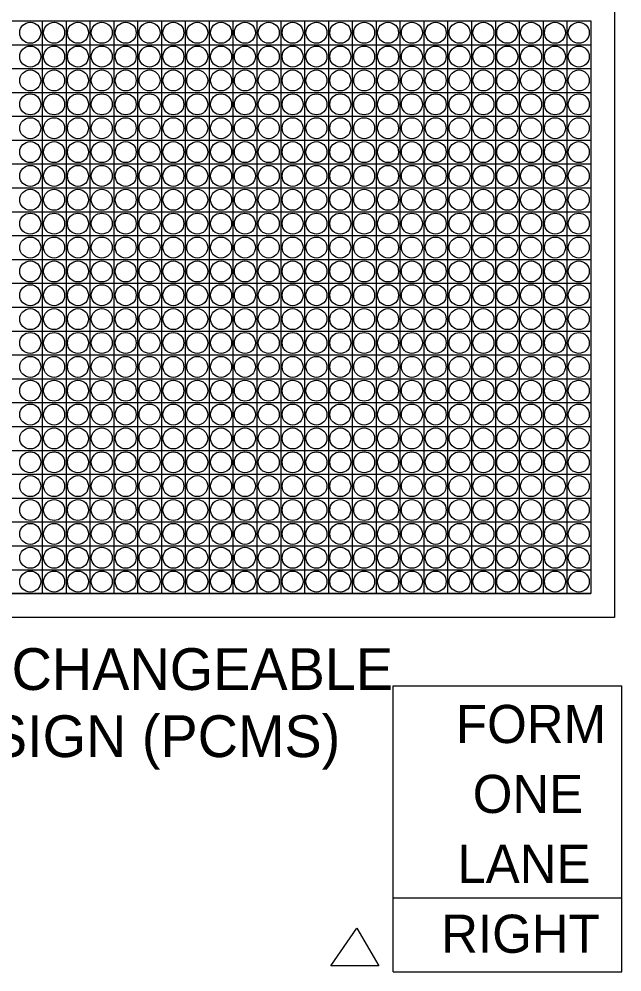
# Model space of a CAD drawing. Extents: x 15278 to 18126, y 1908 to 6555.
# Drawn here: x 16378.4 to 16479.5, y 2488.5 to 2648.2 of the extents above; entities that cross this region are included whole.
import ezdxf

# ---------------------------------------------------------------- set-up
doc = ezdxf.new("R2010")
doc.units = 0
for name, color, linetype in [('TRAFFIC_SIGNS_PR', 7, 'Continuous'), ('TYPICAL_TEXT_DIMEN_EX', 7, 'Continuous'), ('TYPICAL_TEXT_DIMEN_PR', 7, 'Continuous')]:
    doc.layers.add(name, color=color, linetype=linetype)

msp = doc.modelspace()

# ---------------------------------------------------------------- linework, layer by layer
at = {"layer": 'TRAFFIC_SIGNS_PR'}
for p, q in [((16382.29, 2647.89), (16382.29, 2551.89)), ((16386.29, 2647.89), (16386.29, 2551.89)), ((16390.29, 2647.89), (16390.29, 2551.89)), ((16394.29, 2647.89), (16394.29, 2551.89)), ((16398.29, 2647.89), (16398.29, 2551.89)), ((16402.29, 2647.89), (16402.29, 2551.89)), ((16406.29, 2647.89), (16406.29, 2551.89)), ((16410.29, 2647.89), (16410.29, 2551.89)), ((16414.29, 2647.89), (16414.29, 2551.89)), ((16418.29, 2647.89), (16418.29, 2551.89)), ((16422.29, 2647.89), (16422.29, 2551.89)), ((16426.29, 2647.89), (16426.29, 2551.89)), ((16430.29, 2647.89), (16430.29, 2551.89)), ((16434.29, 2647.89), (16434.29, 2551.89)), ((16438.29, 2647.89), (16438.29, 2551.89)), ((16442.29, 2647.89), (16442.29, 2551.89)), ((16446.29, 2647.89), (16446.29, 2551.89)), ((16450.29, 2647.89), (16450.29, 2551.89)), ((16454.29, 2647.89), (16454.29, 2551.89)), ((16458.29, 2647.89), (16458.29, 2551.89)), ((16462.29, 2647.89), (16462.29, 2551.89)), ((16466.29, 2647.89), (16466.29, 2551.89)), ((16470.29, 2647.89), (16470.29, 2551.89)), ((16282.29, 2643.89), (16474.29, 2643.89)), ((16282.29, 2639.89), (16474.29, 2639.89)), ((16282.29, 2635.89), (16474.29, 2635.89)), ((16282.29, 2631.89), (16474.29, 2631.89)), ((16282.29, 2627.89), (16474.29, 2627.89)), ((16282.29, 2623.89), (16474.29, 2623.89)), ((16282.29, 2619.89), (16474.29, 2619.89)), ((16282.29, 2615.89), (16474.29, 2615.89)), ((16282.29, 2611.89), (16474.29, 2611.89)), ((16282.29, 2607.89), (16474.29, 2607.89)), ((16282.29, 2603.89), (16474.29, 2603.89)), ((16282.29, 2599.89), (16474.29, 2599.89)), ((16282.29, 2595.89), (16474.29, 2595.89)), ((16282.29, 2591.89), (16474.29, 2591.89)), ((16282.29, 2587.89), (16474.29, 2587.89)), ((16282.29, 2583.89), (16474.29, 2583.89)), ((16282.29, 2579.89), (16474.29, 2579.89)), ((16282.29, 2575.89), (16474.29, 2575.89)), ((16282.29, 2571.89), (16474.29, 2571.89)), ((16282.29, 2567.89), (16474.29, 2567.89)), ((16282.29, 2563.89), (16474.29, 2563.89)), ((16282.29, 2559.89), (16474.29, 2559.89)), ((16282.29, 2555.89), (16474.29, 2555.89)), ((16282.29, 2551.89), (16474.29, 2551.89)), ((16441.17, 2488.47), (16441.17, 2536.42)), ((16441.17, 2536.42), (16479.53, 2536.42)), ((16479.53, 2488.47), (16479.53, 2536.42)), ((16441.17, 2500.87), (16479.53, 2500.87)), ((16441.17, 2488.47), (16479.53, 2488.47))]:
    msp.add_line(p, q, dxfattribs=at)
for points in [[(16278.29, 2651.89), (16478.29, 2651.89), (16478.29, 2547.89), (16278.29, 2547.89)], [(16282.29, 2647.89), (16474.29, 2647.89), (16474.29, 2551.89), (16282.29, 2551.89)]]:
    msp.add_lwpolyline(points, close=True, dxfattribs=at)
at = {"layer": 'TYPICAL_TEXT_DIMEN_EX'}
for centre in [(16380.29, 2645.89), (16384.29, 2645.89), (16388.29, 2645.89), (16392.29, 2645.89), (16396.29, 2645.89), (16400.29, 2645.89), (16404.29, 2645.89), (16408.29, 2645.89), (16412.29, 2645.89), (16416.29, 2645.89), (16420.29, 2645.89), (16424.29, 2645.89), (16428.29, 2645.89), (16432.29, 2645.89), (16436.29, 2645.89), (16440.29, 2645.89), (16444.29, 2645.89), (16448.29, 2645.89), (16452.29, 2645.89), (16456.29, 2645.89), (16460.29, 2645.89), (16464.29, 2645.89), (16468.29, 2645.89), (16472.29, 2645.89), (16380.29, 2641.89), (16384.29, 2641.89), (16388.29, 2641.89), (16392.29, 2641.89), (16396.29, 2641.89), (16400.29, 2641.89), (16404.29, 2641.89), (16408.29, 2641.89), (16412.29, 2641.89), (16416.29, 2641.89), (16420.29, 2641.89), (16424.29, 2641.89), (16428.29, 2641.89), (16432.29, 2641.89), (16436.29, 2641.89), (16440.29, 2641.89), (16444.29, 2641.89), (16448.29, 2641.89), (16452.29, 2641.89), (16456.29, 2641.89), (16460.29, 2641.89), (16464.29, 2641.89), (16468.29, 2641.89), (16472.29, 2641.89), (16380.29, 2637.89), (16384.29, 2637.89), (16388.29, 2637.89), (16392.29, 2637.89), (16396.29, 2637.89), (16400.29, 2637.89), (16404.29, 2637.89), (16408.29, 2637.89), (16412.29, 2637.89), (16416.29, 2637.89), (16420.29, 2637.89), (16424.29, 2637.89), (16428.29, 2637.89), (16432.29, 2637.89), (16436.29, 2637.89), (16440.29, 2637.89), (16444.29, 2637.89), (16448.29, 2637.89), (16452.29, 2637.89), (16456.29, 2637.89), (16460.29, 2637.89), (16464.29, 2637.89), (16468.29, 2637.89), (16472.29, 2637.89), (16380.29, 2633.89), (16384.29, 2633.89), (16388.29, 2633.89), (16392.29, 2633.89), (16396.29, 2633.89), (16400.29, 2633.89), (16404.29, 2633.89), (16408.29, 2633.89), (16412.29, 2633.89), (16416.29, 2633.89), (16420.29, 2633.89), (16424.29, 2633.89), (16428.29, 2633.89), (16432.29, 2633.89), (16436.29, 2633.89), (16440.29, 2633.89), (16444.29, 2633.89), (16448.29, 2633.89), (16452.29, 2633.89), (16456.29, 2633.89), (16460.29, 2633.89), (16464.29, 2633.89), (16468.29, 2633.89), (16472.29, 2633.89), (16380.29, 2629.89), (16384.29, 2629.89), (16388.29, 2629.89), (16392.29, 2629.89), (16396.29, 2629.89), (16400.29, 2629.89), (16404.29, 2629.89), (16408.29, 2629.89), (16412.29, 2629.89), (16416.29, 2629.89), (16420.29, 2629.89), (16424.29, 2629.89), (16428.29, 2629.89), (16432.29, 2629.89), (16436.29, 2629.89), (16440.29, 2629.89), (16444.29, 2629.89), (16448.29, 2629.89), (16452.29, 2629.89), (16456.29, 2629.89), (16460.29, 2629.89), (16464.29, 2629.89), (16468.29, 2629.89), (16472.29, 2629.89), (16380.29, 2625.89), (16384.29, 2625.89), (16388.29, 2625.89), (16392.29, 2625.89), (16396.29, 2625.89), (16400.29, 2625.89), (16404.29, 2625.89), (16408.29, 2625.89), (16412.29, 2625.89), (16416.29, 2625.89), (16420.29, 2625.89), (16424.29, 2625.89), (16428.29, 2625.89), (16432.29, 2625.89), (16436.29, 2625.89), (16440.29, 2625.89), (16444.29, 2625.89), (16448.29, 2625.89), (16452.29, 2625.89), (16456.29, 2625.89), (16460.29, 2625.89), (16464.29, 2625.89), (16468.29, 2625.89), (16472.29, 2625.89), (16380.29, 2621.89), (16384.29, 2621.89), (16388.29, 2621.89), (16392.29, 2621.89), (16396.29, 2621.89), (16400.29, 2621.89), (16404.29, 2621.89), (16408.29, 2621.89), (16412.29, 2621.89), (16416.29, 2621.89), (16420.29, 2621.89), (16424.29, 2621.89), (16428.29, 2621.89), (16432.29, 2621.89), (16436.29, 2621.89), (16440.29, 2621.89), (16444.29, 2621.89), (16448.29, 2621.89), (16452.29, 2621.89), (16456.29, 2621.89), (16460.29, 2621.89), (16464.29, 2621.89), (16468.29, 2621.89), (16472.29, 2621.89), (16380.29, 2617.89), (16384.29, 2617.89), (16388.29, 2617.89), (16392.29, 2617.89), (16396.29, 2617.89), (16400.29, 2617.89), (16404.29, 2617.89), (16408.29, 2617.89), (16412.29, 2617.89), (16416.29, 2617.89), (16420.29, 2617.89), (16424.29, 2617.89), (16428.29, 2617.89), (16432.29, 2617.89), (16436.29, 2617.89), (16440.29, 2617.89), (16444.29, 2617.89), (16448.29, 2617.89), (16452.29, 2617.89), (16456.29, 2617.89), (16460.29, 2617.89), (16464.29, 2617.89), (16468.29, 2617.89), (16472.29, 2617.89), (16380.29, 2613.89), (16384.29, 2613.89), (16388.29, 2613.89), (16392.29, 2613.89), (16396.29, 2613.89), (16400.29, 2613.89), (16404.29, 2613.89), (16408.29, 2613.89), (16412.29, 2613.89), (16416.29, 2613.89), (16420.29, 2613.89), (16424.29, 2613.89), (16428.29, 2613.89), (16432.29, 2613.89), (16436.29, 2613.89), (16440.29, 2613.89), (16444.29, 2613.89), (16448.29, 2613.89), (16452.29, 2613.89), (16456.29, 2613.89), (16460.29, 2613.89), (16464.29, 2613.89), (16468.29, 2613.89), (16472.29, 2613.89), (16380.29, 2609.89), (16384.29, 2609.89), (16388.29, 2609.89), (16392.29, 2609.89), (16396.29, 2609.89), (16400.29, 2609.89), (16404.29, 2609.89), (16408.29, 2609.89), (16412.29, 2609.89), (16416.29, 2609.89), (16420.29, 2609.89), (16424.29, 2609.89), (16428.29, 2609.89), (16432.29, 2609.89), (16436.29, 2609.89), (16440.29, 2609.89), (16444.29, 2609.89), (16448.29, 2609.89), (16452.29, 2609.89), (16456.29, 2609.89), (16460.29, 2609.89), (16464.29, 2609.89), (16468.29, 2609.89), (16472.29, 2609.89), (16380.29, 2605.89), (16384.29, 2605.89), (16388.29, 2605.89), (16392.29, 2605.89), (16396.29, 2605.89), (16400.29, 2605.89), (16404.29, 2605.89), (16408.29, 2605.89), (16412.29, 2605.89), (16416.29, 2605.89), (16420.29, 2605.89), (16424.29, 2605.89), (16428.29, 2605.89), (16432.29, 2605.89), (16436.29, 2605.89), (16440.29, 2605.89), (16444.29, 2605.89), (16448.29, 2605.89), (16452.29, 2605.89), (16456.29, 2605.89), (16460.29, 2605.89), (16464.29, 2605.89), (16468.29, 2605.89), (16472.29, 2605.89), (16380.29, 2601.89), (16384.29, 2601.89), (16388.29, 2601.89), (16392.29, 2601.89), (16396.29, 2601.89), (16400.29, 2601.89), (16404.29, 2601.89), (16408.29, 2601.89), (16412.29, 2601.89), (16416.29, 2601.89), (16420.29, 2601.89), (16424.29, 2601.89), (16428.29, 2601.89), (16432.29, 2601.89), (16436.29, 2601.89), (16440.29, 2601.89), (16444.29, 2601.89), (16448.29, 2601.89), (16452.29, 2601.89), (16456.29, 2601.89), (16460.29, 2601.89), (16464.29, 2601.89), (16468.29, 2601.89), (16472.29, 2601.89), (16380.29, 2597.89), (16384.29, 2597.89), (16388.29, 2597.89), (16392.29, 2597.89), (16396.29, 2597.89), (16400.29, 2597.89), (16404.29, 2597.89), (16408.29, 2597.89), (16412.29, 2597.89), (16416.29, 2597.89), (16420.29, 2597.89), (16424.29, 2597.89), (16428.29, 2597.89), (16432.29, 2597.89), (16436.29, 2597.89), (16440.29, 2597.89), (16444.29, 2597.89), (16448.29, 2597.89), (16452.29, 2597.89), (16456.29, 2597.89), (16460.29, 2597.89), (16464.29, 2597.89), (16468.29, 2597.89), (16472.29, 2597.89), (16380.29, 2593.89), (16384.29, 2593.89), (16388.29, 2593.89), (16392.29, 2593.89), (16396.29, 2593.89), (16400.29, 2593.89), (16404.29, 2593.89), (16408.29, 2593.89), (16412.29, 2593.89), (16416.29, 2593.89), (16420.29, 2593.89), (16424.29, 2593.89), (16428.29, 2593.89), (16432.29, 2593.89), (16436.29, 2593.89), (16440.29, 2593.89), (16444.29, 2593.89), (16448.29, 2593.89), (16452.29, 2593.89), (16456.29, 2593.89), (16460.29, 2593.89), (16464.29, 2593.89), (16468.29, 2593.89), (16472.29, 2593.89), (16380.29, 2589.89), (16384.29, 2589.89), (16388.29, 2589.89), (16392.29, 2589.89), (16396.29, 2589.89), (16400.29, 2589.89), (16404.29, 2589.89), (16408.29, 2589.89), (16412.29, 2589.89), (16416.29, 2589.89), (16420.29, 2589.89), (16424.29, 2589.89), (16428.29, 2589.89), (16432.29, 2589.89), (16436.29, 2589.89), (16440.29, 2589.89), (16444.29, 2589.89), (16448.29, 2589.89), (16452.29, 2589.89), (16456.29, 2589.89), (16460.29, 2589.89), (16464.29, 2589.89), (16468.29, 2589.89), (16472.29, 2589.89), (16380.29, 2585.89), (16384.29, 2585.89), (16388.29, 2585.89), (16392.29, 2585.89), (16396.29, 2585.89), (16400.29, 2585.89), (16404.29, 2585.89), (16408.29, 2585.89), (16412.29, 2585.89), (16416.29, 2585.89), (16420.29, 2585.89), (16424.29, 2585.89), (16428.29, 2585.89), (16432.29, 2585.89), (16436.29, 2585.89), (16440.29, 2585.89), (16444.29, 2585.89), (16448.29, 2585.89), (16452.29, 2585.89), (16456.29, 2585.89), (16460.29, 2585.89), (16464.29, 2585.89), (16468.29, 2585.89), (16472.29, 2585.89), (16380.29, 2581.89), (16384.29, 2581.89), (16388.29, 2581.89), (16392.29, 2581.89), (16396.29, 2581.89), (16400.29, 2581.89), (16404.29, 2581.89), (16408.29, 2581.89), (16412.29, 2581.89), (16416.29, 2581.89), (16420.29, 2581.89), (16424.29, 2581.89), (16428.29, 2581.89), (16432.29, 2581.89), (16436.29, 2581.89), (16440.29, 2581.89), (16444.29, 2581.89), (16448.29, 2581.89), (16452.29, 2581.89), (16456.29, 2581.89), (16460.29, 2581.89), (16464.29, 2581.89), (16468.29, 2581.89), (16472.29, 2581.89), (16380.29, 2577.89), (16384.29, 2577.89), (16388.29, 2577.89), (16392.29, 2577.89), (16396.29, 2577.89), (16400.29, 2577.89), (16404.29, 2577.89), (16408.29, 2577.89), (16412.29, 2577.89), (16416.29, 2577.89), (16420.29, 2577.89), (16424.29, 2577.89), (16428.29, 2577.89), (16432.29, 2577.89), (16436.29, 2577.89), (16440.29, 2577.89), (16444.29, 2577.89), (16448.29, 2577.89), (16452.29, 2577.89), (16456.29, 2577.89), (16460.29, 2577.89), (16464.29, 2577.89), (16468.29, 2577.89), (16472.29, 2577.89), (16380.29, 2573.89), (16384.29, 2573.89), (16388.29, 2573.89), (16392.29, 2573.89), (16396.29, 2573.89), (16400.29, 2573.89), (16404.29, 2573.89), (16408.29, 2573.89), (16412.29, 2573.89), (16416.29, 2573.89), (16420.29, 2573.89), (16424.29, 2573.89), (16428.29, 2573.89), (16432.29, 2573.89), (16436.29, 2573.89), (16440.29, 2573.89), (16444.29, 2573.89), (16448.29, 2573.89), (16452.29, 2573.89), (16456.29, 2573.89), (16460.29, 2573.89), (16464.29, 2573.89), (16468.29, 2573.89), (16472.29, 2573.89), (16380.29, 2569.89), (16384.29, 2569.89), (16388.29, 2569.89), (16392.29, 2569.89), (16396.29, 2569.89), (16400.29, 2569.89), (16404.29, 2569.89), (16408.29, 2569.89), (16412.29, 2569.89), (16416.29, 2569.89), (16420.29, 2569.89), (16424.29, 2569.89), (16428.29, 2569.89), (16432.29, 2569.89), (16436.29, 2569.89), (16440.29, 2569.89), (16444.29, 2569.89), (16448.29, 2569.89), (16452.29, 2569.89), (16456.29, 2569.89), (16460.29, 2569.89), (16464.29, 2569.89), (16468.29, 2569.89), (16472.29, 2569.89), (16380.29, 2565.89), (16384.29, 2565.89), (16388.29, 2565.89), (16392.29, 2565.89), (16396.29, 2565.89), (16400.29, 2565.89), (16404.29, 2565.89), (16408.29, 2565.89), (16412.29, 2565.89), (16416.29, 2565.89), (16420.29, 2565.89), (16424.29, 2565.89), (16428.29, 2565.89), (16432.29, 2565.89), (16436.29, 2565.89), (16440.29, 2565.89), (16444.29, 2565.89), (16448.29, 2565.89), (16452.29, 2565.89), (16456.29, 2565.89), (16460.29, 2565.89), (16464.29, 2565.89), (16468.29, 2565.89), (16472.29, 2565.89), (16380.29, 2561.89), (16384.29, 2561.89), (16388.29, 2561.89), (16392.29, 2561.89), (16396.29, 2561.89), (16400.29, 2561.89), (16404.29, 2561.89), (16408.29, 2561.89), (16412.29, 2561.89), (16416.29, 2561.89), (16420.29, 2561.89), (16424.29, 2561.89), (16428.29, 2561.89), (16432.29, 2561.89), (16436.29, 2561.89), (16440.29, 2561.89), (16444.29, 2561.89), (16448.29, 2561.89), (16452.29, 2561.89), (16456.29, 2561.89), (16460.29, 2561.89), (16464.29, 2561.89), (16468.29, 2561.89), (16472.29, 2561.89), (16380.29, 2557.89), (16384.29, 2557.89), (16388.29, 2557.89), (16392.29, 2557.89), (16396.29, 2557.89), (16400.29, 2557.89), (16404.29, 2557.89), (16408.29, 2557.89), (16412.29, 2557.89), (16416.29, 2557.89), (16420.29, 2557.89), (16424.29, 2557.89), (16428.29, 2557.89), (16432.29, 2557.89), (16436.29, 2557.89), (16440.29, 2557.89), (16444.29, 2557.89), (16448.29, 2557.89), (16452.29, 2557.89), (16456.29, 2557.89), (16460.29, 2557.89), (16464.29, 2557.89), (16468.29, 2557.89), (16472.29, 2557.89), (16380.29, 2553.89), (16384.29, 2553.89), (16388.29, 2553.89), (16392.29, 2553.89), (16396.29, 2553.89), (16400.29, 2553.89), (16404.29, 2553.89), (16408.29, 2553.89), (16412.29, 2553.89), (16416.29, 2553.89), (16420.29, 2553.89), (16424.29, 2553.89), (16428.29, 2553.89), (16432.29, 2553.89), (16436.29, 2553.89), (16440.29, 2553.89), (16444.29, 2553.89), (16448.29, 2553.89), (16452.29, 2553.89), (16456.29, 2553.89), (16460.29, 2553.89), (16464.29, 2553.89), (16468.29, 2553.89), (16472.29, 2553.89)]:
    msp.add_circle(centre, 1.76, dxfattribs=at)
at = {"layer": 'TYPICAL_TEXT_DIMEN_PR'}
msp.add_lwpolyline([(16430.71, 2489.5), (16435.07, 2495.8), (16438.77, 2489.5)], close=True, dxfattribs=at)

# ---------------------------------------------------------------- texts
at = {"layer": 'TRAFFIC_SIGNS_PR'}
for s, height, p in [('PORTABLE CHANGEABLE', 7, (16324.62, 2535.73)), ('FORM', 6.394, (16451.69, 2526.83)), ('MESSAGE SIGN (PCMS)', 7, (16324.62, 2524.48)), ('ONE', 6.394, (16454.5, 2515.11)), ('LANE', 6.394, (16451.92, 2503.39)), ('RIGHT', 6.394, (16449.21, 2491.67))]:
    msp.add_text(s, height=height, dxfattribs=at).set_placement(p)

doc.saveas('drawing.dxf')
